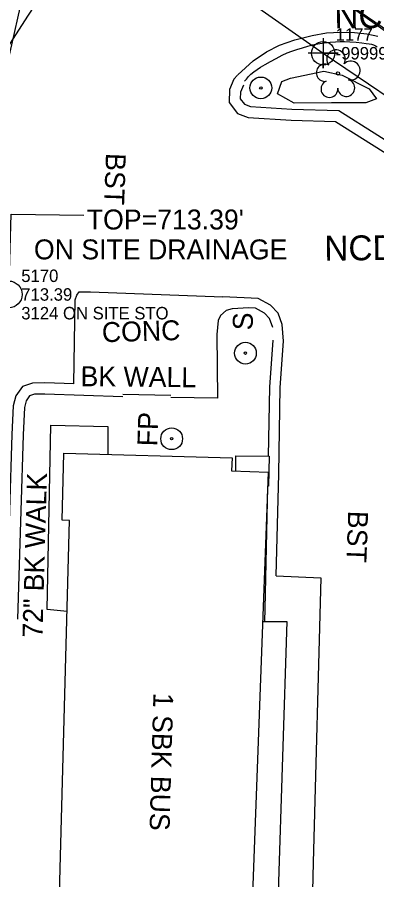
# Model space of a CAD drawing. Extents: x 1516784 to 1522736, y 634838 to 639369.
# Drawn here: x 1520280.1 to 1520352.2, y 637372.3 to 637545.3 of the extents above; entities that cross this region are included whole.
import ezdxf

# ---------------------------------------------------------------- set-up
doc = ezdxf.new("R2010")
doc.units = 0
for name, color, linetype in [('COGO Default Point Number', 7, 'Continuous'), ('Exist Building', 7, 'Continuous'), ('Exist Building Metal Canopy', 7, 'Continuous'), ('Exist Building Text', 7, 'Continuous'), ('Exist Environmental Wetland Boundary Cogo Elevation', 7, 'Continuous'), ('Exist Environmental Wetland Boundary Cogo Number', 7, 'Continuous'), ('Exist Environmental Wetland Boundary Cogo Point CELL', 7, 'Continuous'), ('Exist Other Culture Area Outline', 7, 'Continuous'), ('Exist Other Culture Area Outline Text', 7, 'Continuous'), ('Exist Other Culture Located Object CELL', 7, 'Continuous'), ('Exist Other Culture Sign CELL', 7, 'Continuous'), ('Exist Other Culture Sign Text', 7, 'Continuous'), ('Exist Right of Way Line', 7, 'Continuous'), ('Exist Roads Change in Surface Text', 7, 'Continuous'), ('Exist Roads Curbs Text', 7, 'Continuous'), ('Exist Roads EOP Other Text', 7, 'Continuous'), ('Exist Structure Minor Storm Sewer Manhole CELL', 7, 'Continuous'), ('Exist Structure Minor Storm Sewer Manhole Cogo Comment', 7, 'Continuous'), ('Exist Structure Minor Storm Sewer Manhole Cogo Elevation', 7, 'Continuous'), ('Exist Structure Minor Storm Sewer Manhole Cogo Number', 7, 'Continuous'), ('Exist Structure Minor Storm Sewer Manhole Leader', 7, 'Continuous'), ('Exist Structure Minor Storm Sewer Manhole Text', 7, 'Continuous'), ('Exist Utilities Power UG Cable SUE LOS B Text', 7, 'Continuous'), ('Exist Utilities Sanitary Sewer UG Line', 7, 'Continuous'), ('Exist Utilities Water UG Line SUE LOS B', 7, 'Continuous'), ('Exist Utilities Water UG Line SUE LOS B Cogo Elevation', 7, 'Continuous'), ('Exist Utilities Water UG Line SUE LOS B Cogo Number', 7, 'Continuous'), ('Exist Utilities Water UG Line SUE LOS B Cogo Point CELL', 7, 'Continuous'), ('Exist Vegetation Hedge Row', 7, 'Continuous'), ('Exist Vegetation Tree CELL', 7, 'Continuous'), ('Scratch_Level_5', 7, 'Continuous')]:
    doc.layers.add(name, color=color, linetype=linetype)

msp = doc.modelspace()

# ---------------------------------------------------------------- linework, layer by layer
at = {"layer": 'COGO Default Point Number'}
msp.add_lwpolyline([(1520324.3, 637533.74), (1520327.43, 637536.57), (1520330.06, 637538.38), (1520332.68, 637539.72), (1520335.76, 637540.75), (1520339.2, 637541.64), (1520342.14, 637542.2), (1520344.94, 637542.35), (1520347.73, 637542.25), (1520350.19, 637541.95), (1520352.41, 637541.49)], dxfattribs=at)
at = {"layer": 'Exist Building'}
msp.add_lwpolyline([(1520287.9, 637344.62), (1520290.55, 637444.38), (1520289.08, 637444.42), (1520289.44, 637457.88), (1520323.16, 637456.9), (1520323.06, 637454.35), (1520330.4, 637454.08), (1520326.36, 637344.18), (1520326.34, 637343.67), (1520326.28, 637342.06), (1520317.73, 637342.38), (1520317.77, 637343.53)], close=True, dxfattribs=at)
at = {"layer": 'Exist Building Metal Canopy'}
for points in [[(1520323.9, 637454.32), (1520323.9, 637457.34), (1520330.6, 637457.25), (1520330.46, 637451.24), (1520330.3, 637451.24)], [(1520329.3, 637424.1), (1520334.13, 637424.11), (1520332.4, 637369.78), (1520327.3, 637369.72)]]:
    msp.add_lwpolyline(points, dxfattribs=at)
at = {"layer": 'Exist Environmental Wetland Boundary Cogo Elevation'}
for points in [[(1520291.41, 637471.78), (1520291.7, 637488.65), (1520292.02, 637489.56), (1520292.53, 637490.21), (1520294.79, 637490.22), (1520321.33, 637489.25)], [(1520332.04, 637433.25), (1520340.94, 637432.87), (1520339.42, 637375.76), (1520339.01, 637358.42), (1520338.8, 637345.6), (1520338.58, 637340.45), (1520338.33, 637336.8), (1520337.65, 637333.07), (1520335.42, 637326.18), (1520330.32, 637315.81), (1520324.72, 637306.87), (1520317.62, 637297.56), (1520313.49, 637293.52), (1520309.75, 637291.34), (1520305.26, 637289.8), (1520300.34, 637289.03), (1520295.68, 637289.02), (1520291.65, 637289.38)]]:
    msp.add_lwpolyline(points, dxfattribs=at)
at = {"layer": 'Exist Environmental Wetland Boundary Cogo Number'}
for points in [[(1520325.69, 637532.47), (1520326.04, 637532.92), (1520326.47, 637533.4), (1520326.96, 637533.86), (1520327.53, 637534.33), (1520328.17, 637534.81), (1520328.89, 637535.32), (1520329.78, 637535.86), (1520330.85, 637536.44), (1520332, 637537.05), (1520333.2, 637537.67), (1520334.24, 637538.15), (1520335.15, 637538.48), (1520336.16, 637538.82), (1520337.29, 637539.18), (1520338.33, 637539.49), (1520339.29, 637539.75), (1520340.39, 637539.97), (1520341.63, 637540.16), (1520342.81, 637540.29), (1520343.9, 637540.37), (1520344.85, 637540.42), (1520345.72, 637540.43), (1520346.8, 637540.39), (1520348.07, 637540.29), (1520349.18, 637540.18), (1520350.05, 637540.07), (1520350.69, 637539.98), (1520351.14, 637539.89), (1520351.53, 637539.76), (1520351.91, 637539.57), (1520352.26, 637539.35)], [(1520325.44, 637531.68), (1520324.85, 637530.3), (1520324.8, 637528.94), (1520325.65, 637527.87), (1520326.86, 637527.4), (1520335.14, 637526.86), (1520344.57, 637526.63), (1520360.24, 637516.72), (1520366.98, 637510.25), (1520375.31, 637501.42), (1520379.27, 637494.52), (1520378.8, 637484.69), (1520379.44, 637484.69), (1520379.18, 637480.33), (1520378.8, 637480.4), (1520378.19, 637461.81), (1520377.57, 637442.72), (1520376.65, 637420.26), (1520375.97, 637395.89), (1520375.34, 637376.51), (1520374.17, 637343.49)], [(1520331.33, 637483.05), (1520330.69, 637484.91), (1520329.67, 637485.97), (1520327.86, 637486.93), (1520326.51, 637487), (1520323.17, 637486.84), (1520321.99, 637486.47), (1520320.88, 637485.51), (1520320.38, 637484.47), (1520320.12, 637481.69), (1520320.24, 637468.93), (1520310.88, 637469.03)], [(1520330.49, 637457.25), (1520330.75, 637471.12), (1520331.42, 637480.5)], [(1520301.24, 637469.18), (1520285.59, 637469.71), (1520283.53, 637469.68), (1520282.56, 637469.34), (1520281.87, 637468.37), (1520281.52, 637467.03), (1520281.28, 637461.53), (1520280.78, 637446.31), (1520280.1, 637424.55)], [(1520329.72, 637424.1), (1520329.8, 637426.72), (1520330.37, 637451.24)]]:
    msp.add_lwpolyline(points, dxfattribs=at)
at = {"layer": 'Exist Environmental Wetland Boundary Cogo Point CELL'}
for p, q in [((1520328.41, 637488.9), (1520321.33, 637489.25)), ((1520333.5, 637480.35), (1520333.22, 637483.7)), ((1520301.25, 637469.68), (1520310.88, 637469.53))]:
    msp.add_line(p, q, dxfattribs=at)
for points in [[(1520236.48, 637454.3), (1520236.7, 637457.75), (1520249.16, 637465.12), (1520254.1, 637468.04), (1520255.27, 637469.59), (1520255.86, 637471.88), (1520254.41, 637474.23), (1520252.17, 637475.46), (1520240.16, 637474.85), (1520239.96, 637480.88), (1520256.07, 637505.36), (1520269.95, 637526.62), (1520282.37, 637545.71), (1520285.17, 637550.09), (1520296.97, 637548.81), (1520303.69, 637548.25), (1520304.97, 637548.7)], [(1520324.23, 637533.67), (1520323.54, 637532.87), (1520322.65, 637530.79), (1520322.56, 637528.2), (1520324.28, 637526.02), (1520326.38, 637525.21), (1520335.04, 637524.65), (1520343.9, 637524.43), (1520358.86, 637514.96)], [(1520333.22, 637483.7), (1520332.44, 637485.98), (1520330.89, 637487.58), (1520328.41, 637488.9)], [(1520332.04, 637433.25), (1520332.52, 637453.73), (1520332.84, 637471.02), (1520333.5, 637480.35)], [(1520291.41, 637471.78), (1520285.61, 637471.98), (1520283.12, 637471.94), (1520281.13, 637471.23), (1520279.78, 637469.35), (1520279.27, 637467.37), (1520279.02, 637461.62), (1520278.52, 637446.39), (1520277.84, 637424.62)]]:
    msp.add_lwpolyline(points, dxfattribs=at)
at = {"layer": 'Exist Other Culture Area Outline'}
msp.add_lwpolyline([(1520290.07, 637426.12), (1520286.11, 637426.52), (1520286.85, 637463.46), (1520298.27, 637463.2), (1520298.22, 637457.63)], dxfattribs=at)
at = {"layer": 'Exist Other Culture Located Object CELL'}
for centre, radius in [((1520328.94, 637531.14), 2.18), ((1520328.94, 637531.14), 0.24), ((1520311.05, 637460.75), 2.18), ((1520311.05, 637460.75), 0.24)]:
    msp.add_circle(centre, radius, dxfattribs=at)
at = {"layer": 'Exist Other Culture Sign CELL'}
for radius in [2.18, 0.24]:
    msp.add_circle((1520325.85, 637477.93), radius, dxfattribs=at)
at = {"layer": 'Exist Right of Way Line'}
msp.add_line((1520245.65, 637617.28), (1520392.38, 637516.53), dxfattribs=at)
at = {"layer": 'Exist Structure Minor Storm Sewer Manhole CELL'}
msp.add_circle((1520278.39, 637489.7), 2.69, dxfattribs=at)
at = {"layer": 'Exist Structure Minor Storm Sewer Manhole Leader'}
msp.add_lwpolyline([(1520278.39, 637489.7), (1520278.86, 637505.79), (1520293.43, 637505.6)], dxfattribs=at)
at = {"layer": 'Exist Utilities Sanitary Sewer UG Line'}
for p, q in [((1520289.58, 637586.93), (1520252.4, 637422.76)), ((1520402, 637508.25), (1520291.04, 637587.26))]:
    msp.add_line(p, q, dxfattribs=at)
at = {"layer": 'Exist Utilities Water UG Line SUE LOS B'}
msp.add_lwpolyline([(1520296.98, 637588.5), (1520298.04, 637580.19), (1520299.08, 637576.86), (1520300.98, 637567.26), (1520302.73, 637565.14), (1520306.88, 637562.04), (1520323.66, 637550.6), (1520341.44, 637538.09), (1520363.95, 637522.88), (1520369.43, 637518.69)], dxfattribs=at)
at = {"layer": 'Exist Utilities Water UG Line SUE LOS B Cogo Point CELL'}
msp.add_lwpolyline([(1520341.44, 637541.09), (1520341.44, 637535.09), (1520341.44, 637538.09), (1520344.44, 637538.09), (1520338.44, 637538.09)], dxfattribs=at)
msp.add_circle((1520341.44, 637538.09), 2.34, dxfattribs=at)
at = {"layer": 'Exist Vegetation Hedge Row'}
msp.add_lwpolyline([(1520334.91, 637533.06), (1520341.59, 637534.52), (1520345.25, 637533.71), (1520350.65, 637530.93), (1520352.16, 637528.97), (1520349.97, 637528.11), (1520343.14, 637528.14), (1520335.6, 637528.07), (1520332.27, 637529.95), (1520333.18, 637532.44), (1520334.91, 637533.06)], dxfattribs=at)
at = {"layer": 'Exist Vegetation Tree CELL'}
msp.add_line((1520344.4, 637534.03), (1520344.4, 637534.03), dxfattribs=at)
msp.add_circle((1520344.4, 637534.03), 0.326, dxfattribs=at)
for centre, radius, start, end in [((1520344.01, 637536.9), 1.86, 330.1651, 219.7134), ((1520346.95, 637534.62), 1.9, 257.1011, 134.1999), ((1520341.79, 637534.18), 1.73, 62.6636, 279.3457), ((1520346.07, 637531.13), 1.7, 181.2822, 74.56), ((1520342.69, 637530.91), 1.69, 111.5671, 6.231)]:
    msp.add_arc(centre, radius, start, end, dxfattribs=at)

# ---------------------------------------------------------------- texts
at = {"layer": 'Exist Building Text'}
msp.add_text('1 SBK BUS', height=4, rotation=268.3731, dxfattribs=at).set_placement((1520307.4, 637409.83))
at = {"layer": 'Exist Other Culture Area Outline Text'}
msp.add_text('72" BK WALK', height=4, rotation=88.3731, dxfattribs=at).set_placement((1520285.12, 637420.78))
at = {"layer": 'Exist Other Culture Sign Text'}
for s, p in [('S', (1520327.28, 637482.47)), ('FP', (1520308.17, 637459.21))]:
    msp.add_text(s, height=4, rotation=88.3731, dxfattribs=at).set_placement(p)
at = {"layer": 'Exist Roads Change in Surface Text'}
msp.add_text('CONC', height=4, rotation=1.6498, dxfattribs=at).set_placement((1520297.11, 637480.11))
at = {"layer": 'Exist Roads Curbs Text'}
msp.add_text('BK WALL', height=4, rotation=359.4123, dxfattribs=at).set_placement((1520292.76, 637471.31))
at = {"layer": 'Exist Roads EOP Other Text'}
for p in [(1520297.88, 637518.11), (1520346.47, 637446.35)]:
    msp.add_text('BST', height=4, rotation=267.9794, dxfattribs=at).set_placement(p)
at = {"layer": 'Exist Structure Minor Storm Sewer Manhole Cogo Comment'}
msp.add_text('3124 ON SITE STO', height=2.5, dxfattribs=at).set_placement((1520280.89, 637484.7))
at = {"layer": 'Exist Structure Minor Storm Sewer Manhole Cogo Elevation'}
msp.add_text('713.39', height=2.5, dxfattribs=at).set_placement((1520280.89, 637488.45))
at = {"layer": 'Exist Structure Minor Storm Sewer Manhole Cogo Number'}
msp.add_text('5170', height=2.5, dxfattribs=at).set_placement((1520280.89, 637492.2))
at = {"layer": 'Exist Structure Minor Storm Sewer Manhole Text'}
for s, p in [("TOP=713.39'", (1520294.03, 637502.74)), ('ON SITE DRAINAGE', (1520283.43, 637496.74))]:
    msp.add_text(s, height=4, dxfattribs=at).set_placement(p)
at = {"layer": 'Exist Utilities Power UG Cable SUE LOS B Text'}
for p in [(1520343.71, 637543.05), (1520341.7, 637496.47)]:
    msp.add_text('NCDOT Pole', height=5, rotation=0.6235, dxfattribs=at).set_placement(p)
at = {"layer": 'Exist Utilities Water UG Line SUE LOS B Cogo Elevation'}
msp.add_text('-99999.00', height=2.5, dxfattribs=at).set_placement((1520343.94, 637536.84))
at = {"layer": 'Exist Utilities Water UG Line SUE LOS B Cogo Number'}
msp.add_text('1177', height=2.5, dxfattribs=at).set_placement((1520343.94, 637540.59))
at = {"layer": 'Scratch_Level_5'}
msp.add_text('COLUMN LOCATION', height=500, rotation=335.0373, dxfattribs=at).set_placement((1516680.97, 637558.94))

doc.saveas('drawing.dxf')
